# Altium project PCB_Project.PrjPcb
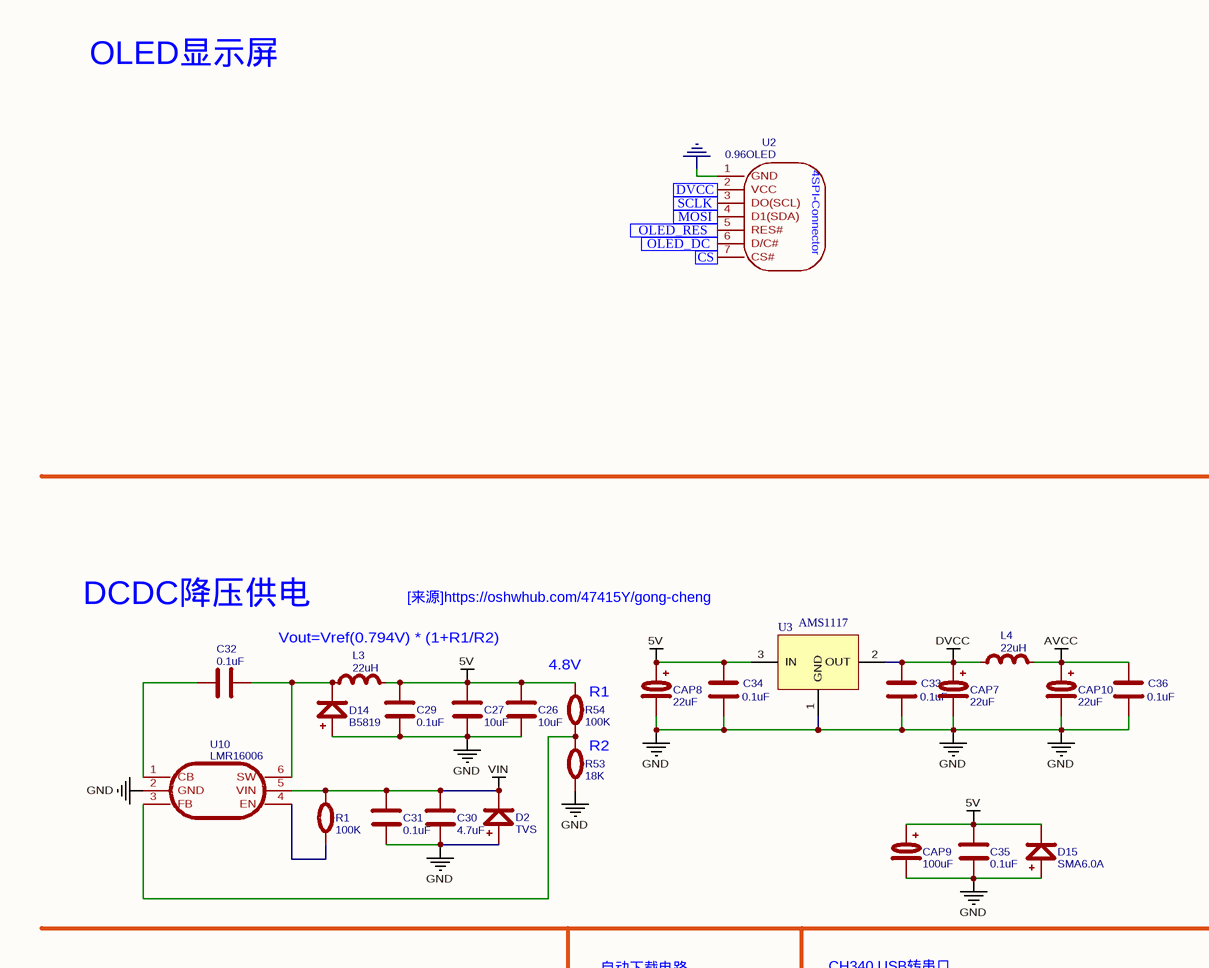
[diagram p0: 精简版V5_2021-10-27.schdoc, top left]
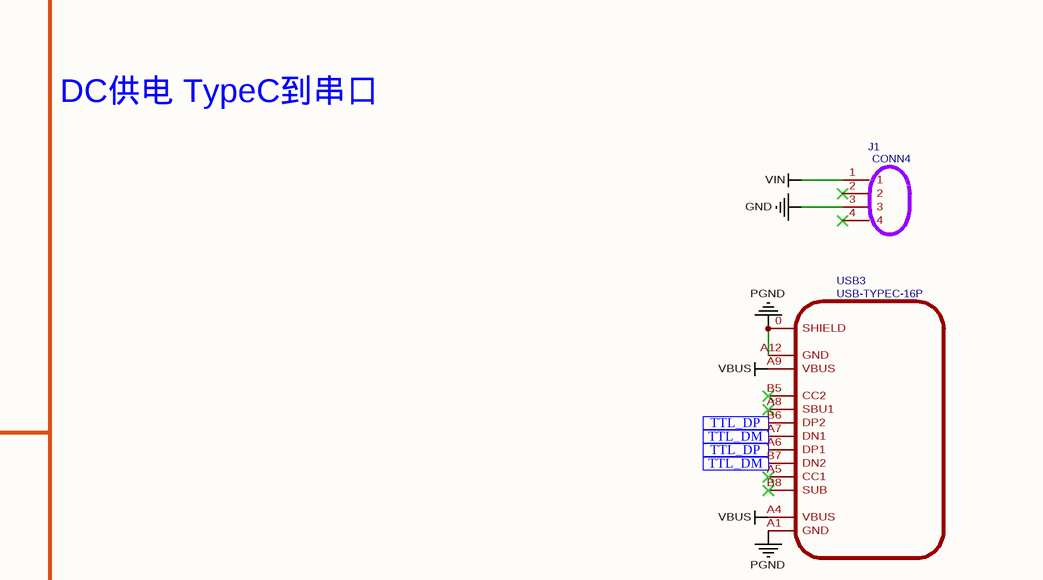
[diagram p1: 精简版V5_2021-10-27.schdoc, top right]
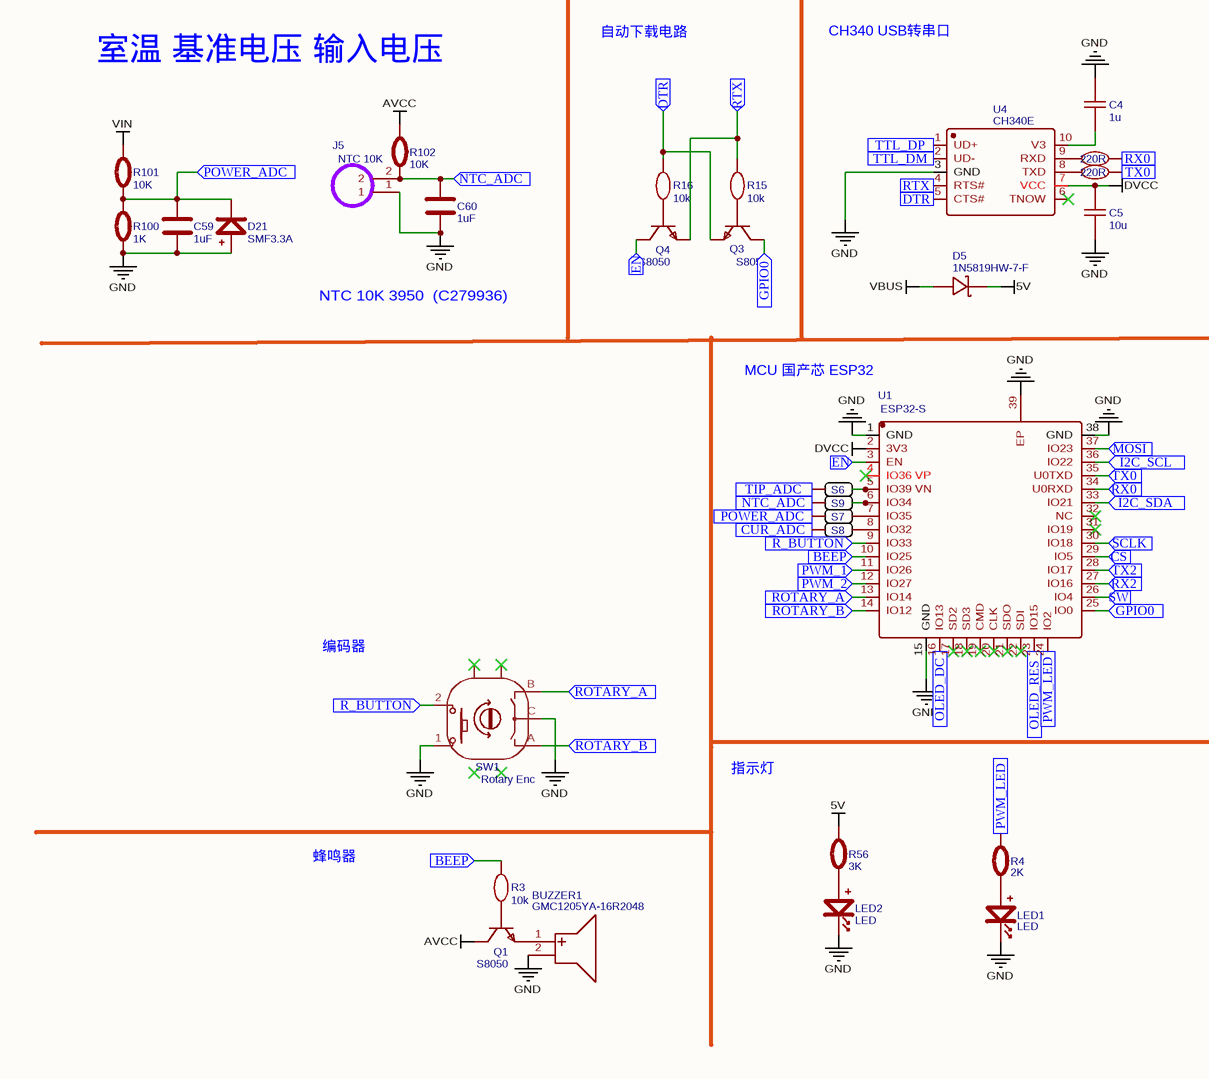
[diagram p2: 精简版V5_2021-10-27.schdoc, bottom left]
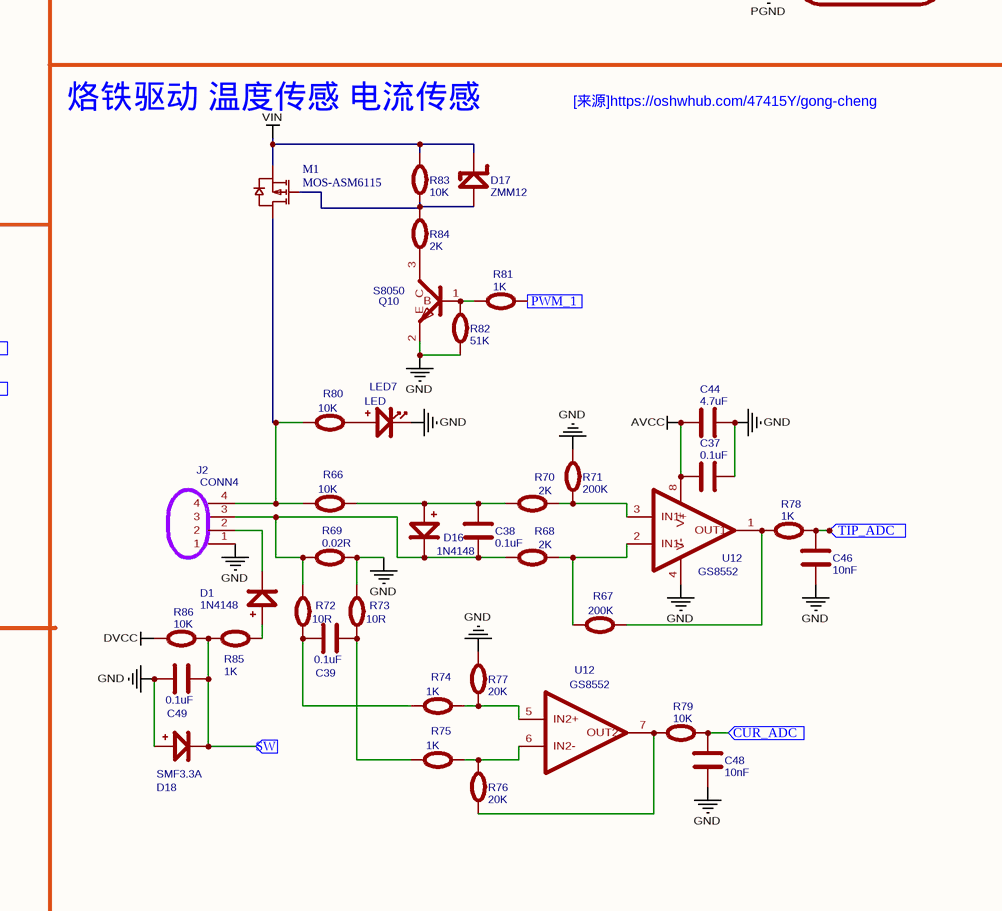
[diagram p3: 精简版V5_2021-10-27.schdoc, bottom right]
1 sheet, 95 parts. Net scope: flat (ports and power ports of the same name join across sheets).
Board files: PCB_OpenT12_精简_2021-10-27.pcbdoc, 精简焊台.PcbDoc

## Sheet 精简版V5_2021-10-27.schdoc
size 430 x 384 mm

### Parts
(Parts that share a designator on the sheet are numbered #1, #2 ... from top to bottom, then left to right.)
BUZZER1  GMC1205YA-16R2048  [BUZ-TH_BD12.0-P6.50-D0.6-FD]
C4  1u  [C0603]
C5  10u  [C0603]
C26  10uF  [电容]
C27  10uF  [电容]
C29  0.1uF  [电容]
C30  4.7uF  [电容]
C31  0.1uF  [0603C]
C32  0.1uF  [0603C]
C33  0.1uF  [0603C]
C34  0.1uF  [0603C]
C35  0.1uF  [0603C]
C36  0.1uF  [0603C]
C37  0.1uF  [0603C]
C38  0.1uF  [0603C]
C39  0.1uF  [0603C]
C44  4.7uF  [电容]
C46  10nF  [0603C]
C48  10nF  [0603C]
C49  0.1uF  [0603C]
C59  1uF  [0603C]
C60  1uF  [0603C]
CAP7  22uF  [CAPX-5.0]
CAP8  22uF  [CAPX-5.0]
CAP9  100uF  [CAPX-5.0]
CAP10  22uF  [CAPX-5.0]
D1  1N4148  [LC-SOD-123]
D2  TVS  [二极管 SMA(DO-214AC)]
D5  1N5819HW-7-F  [SOD-123_L2.8-W1.8-LS3.7-FD]
D14  B5819  [二极管 SMA(DO-214AC)]
D15  SMA6.0A  [LC-SOD-123]
D16  1N4148  [LC-SOD-123]
D17  ZMM12  [LC-SOD-123]
D18  SMF3.3A  [LC-SOD-123]
D21  SMF3.3A  [LC-SOD-123]
J1  CONN4  [SIP-4]
J2  CONN4  [SIP-4]
J5  NTC 10K  [SIP-2]
L3  22uH  [LIN0520]
L4  22uH  [LIN0520]
LED1  LED  [LC-0603-LED]
LED2  LED  [LC-0603-LED]
LED7  LED  [LC-0603-LED]
M1  MOS-ASM6115  [MOS-ASM6115]
Q1  S8050  [SOT-23-3_L2.9-W1.3-P1.90-LS2.4-BR]
Q3  S8050  [SOT-23-3_L2.9-W1.3-P1.90-LS2.4-BR]
Q4  S8050  [SOT-23-3_L2.9-W1.3-P1.90-LS2.4-BR]
Q10  S8050  [LC-SOT-23(SOT-23-3)]
R1  100K  [0603R]
R3  10k  [R0603]
R4  2K  [0603R]
R15  10k  [R0603]
R16  10k  [R0603]
R18  220R  [R0603]
R19  220R  [R0603]
R53  18K  [0603R]
R54  100K  [0603R]
R56  3K  [0603R]
R66  10K  [0603R]
R67  200K  [0603R]
R68  2K  [0603R]
R69  0.02R  [0603R]
R70  2K  [0603R]
R71  200K  [0603R]
R72  10R  [0603R]
R73  10R  [0603R]
R74  1K  [0603R]
R75  1K  [0603R]
R76  20K  [0603R]
R77  20K  [0603R]
R78  1K  [0603R]
R79  10K  [0603R]
R80  10K  [0603R]
R81  1K  [0603R]
R82  51K  [0603R]
R83  10K  [0603R]
R84  2K  [0603R]
R85  1K  [0603R]
R86  10K  [0603R]
R100  1K  [0603R]
R101  10K  [0603R]
R102  10K  [0603R]
S6  Solder  [SW_HAND_WELD_JX]  (value not drawn)
S7  Solder  [SW_HAND_WELD_JX]  (value not drawn)
S8  Solder  [SW_HAND_WELD_JX]  (value not drawn)
S9  Solder  [SW_HAND_WELD_JX]  (value not drawn)
SW1  Rotary Enc  [SW-TH_PEC11R-4XXXF-SXXXX]
U1  ESP32-S  [WIRELM-SMD_ESP32-S]
U2  0.96OLED  [OLED 12864 SPI 7P]
U3  AMS1117  [LDO线性稳压 (SOT-223)]
U4  CH340E  [MSOP-10_L3.0-W3.0-P0.50-LS5.0-BL]
U10  LMR16006  [开关电源 (LMR16006)]
U12#1  GS8552  [LC-SOP-8-150MIL]
U12#2  GS8552  [LC-SOP-8-150MIL]
USB3  USB-TYPEC-16P  [USB-TYPE-C-16P]

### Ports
BEEP (in), CS (in), CUR_ADC (in), DTR (in), DVCC (in), EN (in), GPIO0 (in), I2C_SCL (in), I2C_SDA (in), MOSI (in), NTC_ADC (in), OLED_DC (in), OLED_RES (in), POWER_ADC (in), PWM_1 (in), PWM_2 (in), PWM_LED (in), R_BUTTON (in), ROTARY_A (in), ROTARY_B (in), RTX (in), RX0 (in), RX2 (in), SCLK (in), SW (in), TIP_ADC (in), TTL_DM (in), TTL_DP (in), TX0 (in), TX2 (in)

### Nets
5V: C26.1 C27.1 C29.1 C34.2 C35.1 CAP8.1 CAP9.1 D5.2(K) D15.2 L3.2 R54.2 R56.2 U3.3(IN)
AVCC: C36.2 C37.2 C44.2 CAP10.1 L4.2 Q1.3(C) R102.2 U12#1.8(V+)
DVCC: C5.2 C33.2 CAP7.1 L4.1 R86.1 U1.2(3V3) U3.2(OUT) U4.7(VCC)
GND: BUZZER1.2(-) C4.2 C5.1 C26.2 C27.2 C29.2 C30.2 C31.2 C33.1 C34.1 C35.2 C36.1 C37.1 C44.1 C46.2 C48.2 C49.1 C59.2 C60.2 CAP7.2 CAP8.2 CAP9.2 CAP10.2 D2.1 D14.1 D15.1 D18.1 D21.1 J1.3 J2.1 J5.1 LED1.K LED2.K LED7.K Q10.2(E) R53.1 R69.2 R71.2 R73.2 R77.2 R82.1 R100.1 SW1.1 SW1.C U1.1(GND) U1.15(GND) U1.38(GND) U1.39(EP) U2.1(GND) U3.1(GND) U4.3(GND) U10.2(GND) U12#1.4(V-)
PGND: USB3.0(SHIELD) USB3.A1(GND) USB3.A12(GND)
VBUS: D5.1(A) USB3.A4(VBUS) USB3.A9(VBUS)
VIN: C30.1 C31.1 D2.2 D17.2 J1.1 M1.3(S) R1.2 R83.2 R101.2 U10.5(VIN)
NetBUZZER1_1: BUZZER1.1(+) Q1.2(E)
NetC4_1: C4.1 U4.10(V3)
NetC32_1: C32.1 D14.2 L3.1 U10.6(SW)
NetC32_2: C32.2 U10.1(CB)
NetC38_1: C38.1 D16.1 R66.2 R70.1
NetC38_2: C38.2 D16.2 J2.3 R68.2 R69.1 R72.2
NetC39_1: C39.1 R72.1 R74.1
NetC39_2: C39.2 R73.1 R75.1
NetC46_1: C46.1 R78.1 S6.2 ; port TIP_ADC
NetC48_1: C48.1 R79.1 S8.2 ; port CUR_ADC
NetC49_2: C49.2 D18.2 R85.2 R86.2 U1.26(IO4) ; port SW
NetC59_1: C59.1 D21.2 R100.2 R101.1 S7.2 ; port POWER_ADC
NetC60_1: C60.1 J5.2 R102.1 S9.2 ; port NTC_ADC
NetD1_1: D1.1 R85.1
NetD1_2: D1.2 J2.2
NetD17_1: D17.1 M1.1(G) R83.1 R84.2
NetJ2_4: J2.4 M1.2(D) R66.1 R80.1
NetLED1_A: LED1.A R4.1
NetLED2_A: LED2.A R56.1
NetLED7_A: LED7.A R80.2
NetQ1_1: Q1.1(B) R3.1
NetQ3_1: Q3.1(B) R15.1
NetQ3_2: Q3.2(E) R16.2 U4.5(CTS#) ; port DTR
NetQ3_3: Q3.3(C) U1.25(IO0) ; port GPIO0
NetQ4_1: Q4.1(B) R16.1
NetQ4_2: Q4.2(E) R15.2 U4.4(RTS#) ; port RTX
NetQ4_3: Q4.3(C) U1.3(EN) ; port EN
NetQ10_1: Q10.1(B) R81.2 R82.2
NetQ10_3: Q10.3(C) R84.1
NetR1_1: R1.1 U10.4(EN)
NetR3_2: R3.2 U1.10(IO25) ; port BEEP
NetR4_2: R4.2 U1.24(IO2) ; port PWM_LED
NetR18_1: R18.1 U4.9(RXD)
NetR18_2: R18.2 U1.34(U0RXD) ; port RX0
NetR19_1: R19.1 U4.8(TXD)
NetR19_2: R19.2 U1.35(U0TXD) ; port TX0
NetR53_2: R53.2 R54.1 U10.3(FB)
NetR67_1: R67.1 R68.1 U12#1.2(IN1-)
NetR67_2: R67.2 R78.2 U12#1.1(OUT1)
NetR70_2: R70.2 R71.1 U12#1.3(IN1+)
NetR74_2: R74.2 R77.1 U12#2.5(IN2+)
NetR75_2: R75.2 R76.2 U12#2.6(IN2-)
NetR76_1: R76.1 R79.2 U12#2.7(OUT2)
NetR81_1: R81.1 U1.11(IO26) ; port PWM_1
NetS6_1: S6.1 U1.5(IO39_VN)
NetS7_1: S7.1 U1.7(IO35)
NetS8_1: S8.1 U1.8(IO32)
NetS9_1: S9.1 U1.6(IO34)
NetSW1_2: SW1.2 U1.9(IO33) ; port R_BUTTON
NetSW1_A: SW1.A U1.14(IO12) ; port ROTARY_B
NetSW1_B: SW1.B U1.13(IO14) ; port ROTARY_A
NetU1_12: U1.12(IO27) ; port PWM_2
NetU1_16: U1.16(IO13) U2.6(D/C#) ; port OLED_DC
NetU1_23: U1.23(IO15) U2.5(RES#) ; port OLED_RES
NetU1_27: U1.27(IO16) ; port RX2
NetU1_28: U1.28(IO17) ; port TX2
NetU1_29: U1.29(IO5) U2.7(CS#) ; port CS
NetU1_30: U1.30(IO18) U2.3(DO(SCL)) ; port SCLK
NetU1_33: U1.33(IO21) ; port I2C_SDA
NetU1_36: U1.36(IO22) ; port I2C_SCL
NetU1_37: U1.37(IO23) U2.4(D1(SDA)) ; port MOSI
NetU2_2: U2.2(VCC) ; port DVCC
NetU4_1: U4.1(UD+) USB3.A6(DP1) USB3.B6(DP2) ; port TTL_DP
NetU4_2: U4.2(UD-) USB3.A7(DN1) USB3.B7(DN2) ; port TTL_DM

Not connected (* = marked no-connect by the designer): J1 2* 4*; SW1 MT1* MT2*; U1 4(IO36_VP)* 17(SD2)* 18(SD3)* 19(CMD)* 20(CLK)* 21(SDO)* 22(SDI)* 31(IO19)* 32(NC)*; U4 6(TNOW)*; USB3 A5(CC1)* A8(SBU1)* B5(CC2)* B8(SUB)*

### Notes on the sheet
- OLED显示屏
- DCDC降压供电
- [来源]https://oshwhub.com/47415Y/gong-cheng
- DC供电 TypeC到串口
- Vout=Vref(0.794V) * (1+R1/R2)
- (near R54) 4.8V
- R2
- (near R54) R1
- 室温 基准电压 输入电压
- 自动下载电路
- CH340 USB转串口
- 烙铁驱动 温度传感 电流传感
- NTC 10K 3950  (C279936)
- MCU 国产芯 ESP32
- 编码器
- 指示灯
- 蜂鸣器

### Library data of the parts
BUZZER1 = GMC1205YA-16R2048: BOM_Manufacturer: INGHAi; Contributor: LCSC
C4 = 1u: nameAlias: Value(F); Contributor: LCEDA_Lib
C5 = 10u: nameAlias: Value(F); Contributor: LCEDA_Lib
C26 C27 = 10uF: Contributor: 47415Y
C29 C31-C39 C49 = 0.1uF: Contributor: 47415Y
C30 C44 = 4.7uF: Contributor: 47415Y
C46 C48 = 10nF: Contributor: 47415Y
C59 C60 = 1uF: Contributor: 47415Y
CAP7 CAP8 CAP10 = 22uF: Contributor: 47415Y
CAP9 = 100uF: Contributor: 47415Y
D1 D16 = 1N4148: Contributor: 47415Y
D2 D14 = B5819: Contributor: 47415Y
D5 = 1N5819HW-7-F: BOM_Manufacturer: DIODES; BOM_Paste Type: expand; BOM_Assembly Type: smtWeld
D15 = SMA6.0A: Contributor: 47415Y
D17 = ZMM12: Contributor: 47415Y
D18 D21 = SMF3.3A: Contributor: 47415Y
J1 J2 = CONN4: Contributor: 47415Y
J5 = NTC 10K: Contributor: 47415Y
L3 L4 = 22uH: Contributor: 47415Y
LED1 LED2 LED7 = LED: Contributor: 47415Y
Q1 Q3 Q4 = S8050: BOM_Manufacturer: WPMtek(维攀微); Contributor: LCSC
Q10 = S8050: Contributor: 47415Y
R1 R4 R53 R68 R70 R84 = 2K: Contributor: 47415Y
R3 R15 R16 = 10k: nameAlias: Value(Ω); Contributor: LCEDA_Lib
R18 R19 = 220R: nameAlias: Value(Ω); Contributor: LCEDA_Lib
R54 R66 R79 R80 R83 R86 R101 R102 = 10K: Contributor: 47415Y
R56 = 3K: Contributor: 47415Y
R67 R71 = 200K: Contributor: 47415Y
R69 = 0.02R: Contributor: 47415Y
R72 R73 = 10R: Contributor: 47415Y
R74 R75 R78 R81 R85 R100 = 1K: Contributor: 47415Y
R76 R77 = 20K: Contributor: 47415Y
R82 = 51K: Contributor: 47415Y
S6-S9 = Solder: BOM_Mounted: No
SW1 = Rotary Enc: BOM_Manufacturer: BOURNS; BOM_Manufacturer Part: PEC11R-4015F-S0024; Contributor: LCSC
U1 = ESP32-S: BOM_Manufacturer: Ai-Thinker; Contributor: LCSC; Package Display: No
U2 = 0.96OLED: Contributor: jhsdhdhusdisd
U3 = AMS1117: 线性稳压3.3V-5V 1A
U4 = CH340E: BOM_Manufacturer: WCH; BOM_Paste Type: recommend
U10 = HT7463B: Contributor: 47415Y
U12#1 = GS8552: subpart_no: 1; Contributor: 47415Y
U12#2 = GS8552: subpart_no: 2; Contributor: 47415Y
USB3 = USB-TYPEC-16P: Contributor: 47415Y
